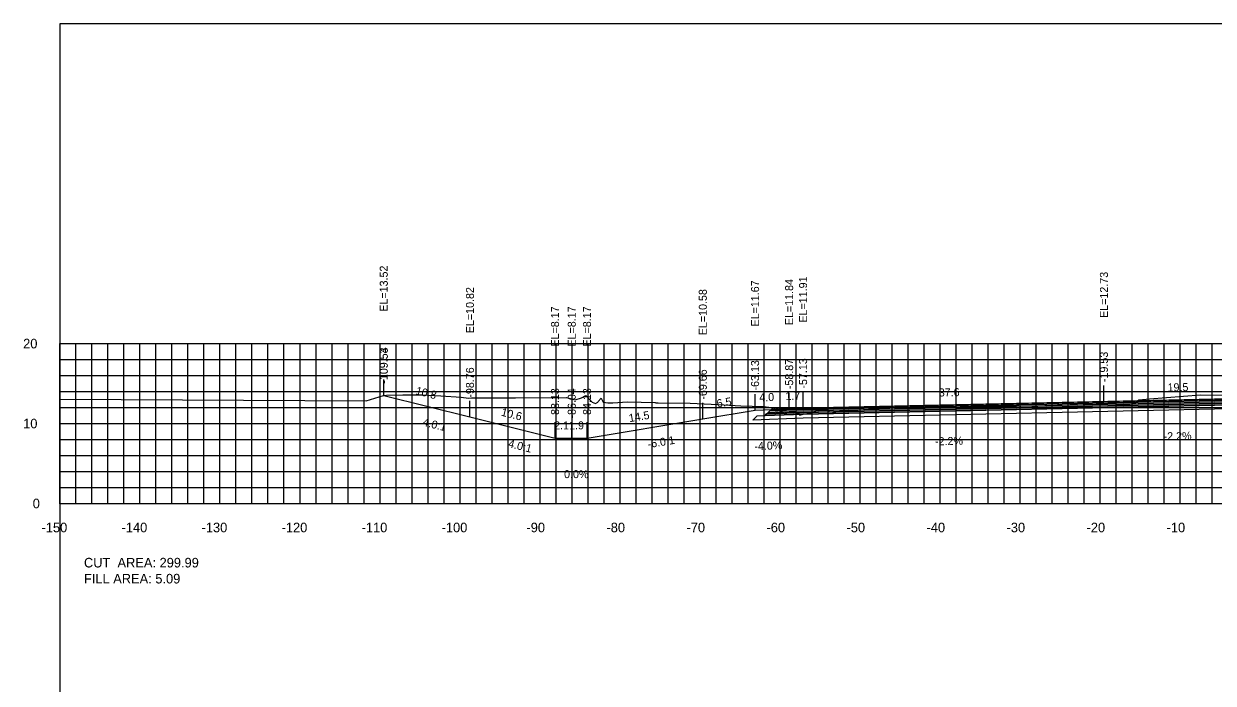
# Model space of a CAD drawing. Extents: x 1797419 to 1809236, y 248759 to 251512.
# Drawn here: x 1802476.5 to 1802625.1, y 250186.9 to 250269.4 of the extents above; entities that cross this region are included whole.
import ezdxf

# ---------------------------------------------------------------- set-up
doc = ezdxf.new("R2010")
doc.units = 0
for name, color, linetype in [('10', 7, 'Continuous'), ('3', 7, 'Continuous'), ('31', 7, 'Continuous'), ('4', 7, 'Continuous'), ('60', 7, 'Continuous'), ('ANNO-TXT', 7, 'Continuous'), ('BASE', 7, 'Continuous'), ('CL-CNST', 7, 'Continuous'), ('Level 62', 7, 'Continuous'), ('LOWER BINDER', 7, 'Continuous'), ('M-ROADS', 7, 'Continuous'), ('UPPER BINDER', 7, 'Continuous'), ('WEARING', 7, 'Continuous')]:
    doc.layers.add(name, color=color, linetype=linetype)

msp = doc.modelspace()

# ---------------------------------------------------------------- linework, layer by layer
for p, q in [((1802521.46, 250222.95), (1802521.46, 250224.95)), ((1802521.47, 250222.95), (1802521.47, 250224.95)), ((1802611.47, 250222.17), (1802611.47, 250224.17)), ((1802567.87, 250221.1), (1802567.87, 250223.1)), ((1802572.13, 250221.27), (1802572.13, 250223.27)), ((1802573.87, 250221.34), (1802573.87, 250223.34)), ((1802573.87, 250221.34), (1802573.87, 250223.34)), ((1802532.24, 250220.26), (1802532.24, 250222.26)), ((1802561.34, 250220.01), (1802561.34, 250222.01)), ((1802542.87, 250217.6), (1802542.87, 250219.6)), ((1802542.87, 250217.6), (1802542.87, 250219.6)), ((1802544.96, 250217.6), (1802544.96, 250219.6)), ((1802546.87, 250217.6), (1802546.87, 250219.6)), ((1802546.87, 250217.6), (1802546.87, 250219.6))]:
    msp.add_line(p, q)
msp.add_lwpolyline([(1802481, 250079.43), (1802781, 250079.43), (1802781, 250269.43), (1802481, 250269.43)], close=True)
at = {"layer": '60'}
for p, q in [((1802480.94, 250229.43), (1802481, 250229.43)), ((1802481, 250209.43), (1802481, 250229.43)), ((1802480.94, 250219.43), (1802481, 250219.43)), ((1802480.94, 250209.43), (1802481, 250209.43)), ((1802481, 250209.43), (1802781, 250209.43)), ((1802481, 250209.37), (1802481, 250209.43)), ((1802491, 250209.37), (1802491, 250209.43)), ((1802501, 250209.37), (1802501, 250209.43)), ((1802511, 250209.37), (1802511, 250209.43)), ((1802521, 250209.37), (1802521, 250209.43)), ((1802531, 250209.37), (1802531, 250209.43)), ((1802541, 250209.37), (1802541, 250209.43)), ((1802551, 250209.37), (1802551, 250209.43)), ((1802561, 250209.37), (1802561, 250209.43)), ((1802571, 250209.37), (1802571, 250209.43)), ((1802581, 250209.37), (1802581, 250209.43)), ((1802591, 250209.37), (1802591, 250209.43)), ((1802601, 250209.37), (1802601, 250209.43)), ((1802611, 250209.37), (1802611, 250209.43)), ((1802621, 250209.37), (1802621, 250209.43))]:
    msp.add_line(p, q, dxfattribs=at)
at = {"layer": 'BASE'}
msp.add_lwpolyline([(1802568.12, 250220.39), (1802569.12, 250220.43), (1802573.87, 250220.62), (1802631, 250221.87), (1802702.76, 250221.87), (1802707.51, 250221.69), (1802708.51, 250221.65), (1802709.03, 250221.12), (1802702.76, 250221.37), (1802631, 250221.37), (1802573.87, 250220.12), (1802567.6, 250219.87)], close=True, dxfattribs=at)
at = {"layer": 'CL-CNST'}
msp.add_lwpolyline([(1802521.46, 250222.95), (1802521.47, 250222.95), (1802532.24, 250220.26), (1802542.87, 250217.6), (1802542.87, 250217.6), (1802544.96, 250217.6), (1802546.87, 250217.6), (1802546.87, 250217.6), (1802561.34, 250220.01), (1802567.87, 250221.1), (1802569.87, 250221.18), (1802570.15, 250221.19), (1802572.13, 250221.27), (1802573.87, 250221.34), (1802573.87, 250221.34), (1802611.47, 250222.17), (1802631, 250222.59)], dxfattribs=at)
at = {"layer": 'Level 62'}
for p, q in [((1802481, 250229.43), (1802781, 250229.43)), ((1802481, 250209.43), (1802481, 250229.43)), ((1802483, 250209.43), (1802483, 250229.43)), ((1802485, 250209.43), (1802485, 250229.43)), ((1802487, 250209.43), (1802487, 250229.43)), ((1802489, 250209.43), (1802489, 250229.43)), ((1802491, 250209.43), (1802491, 250229.43)), ((1802493, 250209.43), (1802493, 250229.43)), ((1802495, 250209.43), (1802495, 250229.43)), ((1802497, 250209.43), (1802497, 250229.43)), ((1802499, 250209.43), (1802499, 250229.43)), ((1802501, 250209.43), (1802501, 250229.43)), ((1802503, 250209.43), (1802503, 250229.43)), ((1802505, 250209.43), (1802505, 250229.43)), ((1802507, 250209.43), (1802507, 250229.43)), ((1802509, 250209.43), (1802509, 250229.43)), ((1802511, 250209.43), (1802511, 250229.43)), ((1802513, 250209.43), (1802513, 250229.43)), ((1802515, 250209.43), (1802515, 250229.43)), ((1802517, 250209.43), (1802517, 250229.43)), ((1802519, 250209.43), (1802519, 250229.43)), ((1802521, 250209.43), (1802521, 250229.43)), ((1802523, 250209.43), (1802523, 250229.43)), ((1802525, 250209.43), (1802525, 250229.43)), ((1802527, 250209.43), (1802527, 250229.43)), ((1802529, 250209.43), (1802529, 250229.43)), ((1802531, 250209.43), (1802531, 250229.43)), ((1802533, 250209.43), (1802533, 250229.43)), ((1802535, 250209.43), (1802535, 250229.43)), ((1802537, 250209.43), (1802537, 250229.43)), ((1802539, 250209.43), (1802539, 250229.43)), ((1802541, 250209.43), (1802541, 250229.43)), ((1802543, 250209.43), (1802543, 250229.43)), ((1802545, 250209.43), (1802545, 250229.43)), ((1802547, 250209.43), (1802547, 250229.43)), ((1802549, 250209.43), (1802549, 250229.43)), ((1802551, 250209.43), (1802551, 250229.43)), ((1802553, 250209.43), (1802553, 250229.43)), ((1802555, 250209.43), (1802555, 250229.43)), ((1802557, 250209.43), (1802557, 250229.43)), ((1802559, 250209.43), (1802559, 250229.43)), ((1802561, 250209.43), (1802561, 250229.43)), ((1802563, 250209.43), (1802563, 250229.43)), ((1802565, 250209.43), (1802565, 250229.43)), ((1802567, 250209.43), (1802567, 250229.43)), ((1802569, 250209.43), (1802569, 250229.43)), ((1802571, 250209.43), (1802571, 250229.43)), ((1802573, 250209.43), (1802573, 250229.43)), ((1802575, 250209.43), (1802575, 250229.43)), ((1802577, 250209.43), (1802577, 250229.43)), ((1802579, 250209.43), (1802579, 250229.43)), ((1802581, 250209.43), (1802581, 250229.43)), ((1802583, 250209.43), (1802583, 250229.43)), ((1802585, 250209.43), (1802585, 250229.43)), ((1802587, 250209.43), (1802587, 250229.43)), ((1802589, 250209.43), (1802589, 250229.43)), ((1802591, 250209.43), (1802591, 250229.43)), ((1802593, 250209.43), (1802593, 250229.43)), ((1802595, 250209.43), (1802595, 250229.43)), ((1802597, 250209.43), (1802597, 250229.43)), ((1802599, 250209.43), (1802599, 250229.43)), ((1802601, 250209.43), (1802601, 250229.43)), ((1802603, 250209.43), (1802603, 250229.43)), ((1802605, 250209.43), (1802605, 250229.43)), ((1802607, 250209.43), (1802607, 250229.43)), ((1802609, 250209.43), (1802609, 250229.43)), ((1802611, 250209.43), (1802611, 250229.43)), ((1802613, 250209.43), (1802613, 250229.43)), ((1802615, 250209.43), (1802615, 250229.43)), ((1802617, 250209.43), (1802617, 250229.43)), ((1802619, 250209.43), (1802619, 250229.43)), ((1802621, 250209.43), (1802621, 250229.43)), ((1802623, 250209.43), (1802623, 250229.43)), ((1802625, 250209.43), (1802625, 250229.43)), ((1802481, 250227.43), (1802781, 250227.43)), ((1802481, 250225.43), (1802781, 250225.43)), ((1802481, 250223.43), (1802781, 250223.43)), ((1802481, 250221.43), (1802781, 250221.43)), ((1802481, 250219.43), (1802781, 250219.43)), ((1802481, 250217.43), (1802781, 250217.43)), ((1802481, 250215.43), (1802781, 250215.43)), ((1802481, 250213.43), (1802781, 250213.43)), ((1802481, 250211.43), (1802781, 250211.43)), ((1802481, 250209.43), (1802781, 250209.43))]:
    msp.add_line(p, q, dxfattribs=at)
at = {"layer": 'LOWER BINDER'}
for points in [[(1802573.87, 250220.81), (1802631, 250222.06), (1802702.76, 250222.06), (1802707.31, 250221.88), (1802707.51, 250221.69), (1802702.76, 250221.87), (1802631, 250221.87), (1802573.87, 250220.62), (1802569.12, 250220.43), (1802569.32, 250220.63)], [(1802573.87, 250221), (1802631, 250222.25), (1802702.76, 250222.25), (1802707.12, 250222.08), (1802707.31, 250221.88), (1802702.76, 250222.06), (1802631, 250222.06), (1802573.87, 250220.81), (1802569.32, 250220.63), (1802569.52, 250220.82)]]:
    msp.add_lwpolyline(points, close=True, dxfattribs=at)
at = {"layer": 'M-ROADS'}
msp.add_lwpolyline([(1802481, 250222.49), (1802519.26, 250222.28), (1802521.44, 250222.95), (1802521.81, 250223), (1802523.87, 250223.02), (1802524.01, 250223.02), (1802524.47, 250223.02), (1802526.23, 250223.01), (1802528.58, 250222.89), (1802531.14, 250222.72), (1802532.04, 250222.6), (1802532.44, 250222.66), (1802534.56, 250222.66), (1802535.31, 250222.66), (1802536.86, 250222.66), (1802537.32, 250222.65), (1802537.48, 250222.64), (1802537.94, 250222.64), (1802544.3, 250222.69), (1802545.37, 250222.41), (1802546.2, 250222.66), (1802546.72, 250222.95), (1802547.51, 250222.11), (1802547.91, 250221.94), (1802548.2, 250222.09), (1802548.26, 250222.17), (1802548.65, 250222.6), (1802548.9, 250222.12), (1802549.47, 250222), (1802549.57, 250222.01), (1802549.87, 250222), (1802550.08, 250222), (1802551.94, 250222.13), (1802555.34, 250222.06), (1802555.38, 250222.08), (1802555.46, 250222.01), (1802555.77, 250222), (1802559.74, 250221.99), (1802563.24, 250221.81), (1802566.11, 250221.64), (1802568.91, 250221.56), (1802569.92, 250221.44), (1802570.26, 250221.12), (1802570.34, 250221.43), (1802570.35, 250221.43), (1802570.85, 250221.23), (1802571.72, 250220.6), (1802572.02, 250220.88), (1802572.78, 250220.87), (1802572.89, 250220.9), (1802573.01, 250220.81), (1802573.35, 250220.64), (1802573.45, 250220.48), (1802573.45, 250220.49), (1802573.59, 250220.51), (1802574.05, 250220.65), (1802574.9, 250220.78), (1802575.24, 250220.91), (1802575.5, 250221.1), (1802575.83, 250221.17), (1802576.67, 250221.2), (1802577.14, 250220.94), (1802577.74, 250220.82), (1802578.04, 250220.92), (1802578.75, 250221.04), (1802584.73, 250221.38), (1802586.78, 250221.43), (1802588.39, 250221.44), (1802588.96, 250221.44), (1802589.1, 250221.43), (1802589.46, 250221.41), (1802590.85, 250221.42), (1802591.73, 250221.43), (1802593.51, 250221.48), (1802597.45, 250221.6), (1802598.27, 250221.63), (1802600.32, 250221.66), (1802600.38, 250221.66), (1802600.4, 250221.66), (1802600.85, 250221.63), (1802601.1, 250221.61), (1802603.03, 250221.64), (1802603.13, 250221.64), (1802603.22, 250221.64), (1802604.08, 250221.67), (1802607.22, 250221.77), (1802610.51, 250221.87), (1802610.68, 250221.88), (1802612.88, 250221.89), (1802613.26, 250221.81), (1802613.33, 250221.84), (1802613.35, 250221.84), (1802613.69, 250221.86), (1802614.41, 250221.87), (1802615.1, 250221.92), (1802615.15, 250221.92), (1802615.24, 250221.93), (1802615.26, 250221.92), (1802615.85, 250222.39), (1802615.85, 250222.39), (1802615.86, 250222.4), (1802617.16, 250222.54), (1802623.55, 250223.04), (1802629.65, 250222.94)], dxfattribs=at)
at = {"layer": 'UPPER BINDER'}
msp.add_lwpolyline([(1802702.76, 250222.25), (1802707.12, 250222.08), (1802706.92, 250222.28), (1802702.76, 250222.44), (1802631, 250222.44), (1802573.87, 250221.19), (1802569.72, 250221.02), (1802569.52, 250220.82), (1802573.87, 250221), (1802631, 250222.25)], close=True, dxfattribs=at)
at = {"layer": 'WEARING'}
msp.add_lwpolyline([(1802702.76, 250222.44), (1802706.92, 250222.28), (1802706.76, 250222.43), (1802702.76, 250222.59), (1802631, 250222.59), (1802573.87, 250221.34), (1802569.87, 250221.18), (1802569.72, 250221.02), (1802573.87, 250221.19), (1802631, 250222.44)], close=True, dxfattribs=at)

# ---------------------------------------------------------------- texts
for s, rotation, p in [('4.0:1', 345.9652, (1802526.25, 250219.18)), ('4.0:1', 345.9652, (1802536.95, 250216.5)), ('-6.0:1', 9.4623, (1802554.52, 250216.34))]:
    msp.add_text(s, height=1, rotation=rotation).set_placement(p)
at = {"layer": '10'}
for s, p in [('-150', (1802478.7, 250205.83)), ('-140', (1802488.7, 250205.83)), ('-130', (1802498.7, 250205.83)), ('-120', (1802508.7, 250205.83)), ('-110', (1802518.7, 250205.83)), ('-100', (1802528.7, 250205.83)), ('-90', (1802539.3, 250205.83)), ('-80', (1802549.3, 250205.83)), ('-70', (1802559.3, 250205.83)), ('-60', (1802569.3, 250205.83)), ('-50', (1802579.3, 250205.83)), ('-40', (1802589.3, 250205.83)), ('-30', (1802599.3, 250205.83)), ('-20', (1802609.3, 250205.83)), ('-10', (1802619.3, 250205.83))]:
    msp.add_text(s, height=1.2, dxfattribs=at).set_placement(p)
at = {"layer": '3'}
for s, p in [('EL=13.52', (1802521.96, 250233.42)), ('EL=13.52', (1802521.97, 250233.42)), ('EL=11.84', (1802572.63, 250231.74)), ('EL=11.91', (1802574.37, 250232.06)), ('EL=11.91', (1802574.37, 250232.06)), ('EL=12.73', (1802611.97, 250232.64)), ('EL=10.82', (1802532.74, 250230.73)), ('EL=10.58', (1802561.84, 250230.48)), ('EL=11.67', (1802568.37, 250231.57)), ('EL=8.17', (1802543.37, 250229.06)), ('EL=8.17', (1802543.37, 250229.06)), ('EL=8.17', (1802545.46, 250229.06)), ('EL=8.17', (1802547.37, 250229.06)), ('EL=8.17', (1802547.37, 250229.06)), ('-109.54', (1802521.96, 250224.42)), ('-109.53', (1802521.97, 250224.41)), ('-63.13', (1802568.37, 250223.56)), ('-58.87', (1802572.63, 250223.73)), ('-57.13', (1802574.37, 250223.8)), ('-57.13', (1802574.37, 250223.8)), ('-19.53', (1802611.97, 250224.62)), ('-98.76', (1802532.74, 250222.67)), ('-69.66', (1802561.84, 250222.42)), ('-88.13', (1802543.37, 250220.06)), ('-88.13', (1802543.37, 250220.06)), ('-86.04', (1802545.46, 250220.06)), ('-84.13', (1802547.37, 250220.06)), ('-84.13', (1802547.37, 250220.06))]:
    msp.add_text(s, height=1, rotation=90, dxfattribs=at).set_placement(p)
at = {"layer": '31'}
for s, p in [('20', (1802476.4, 250228.83)), ('10', (1802476.4, 250218.83)), ('0', (1802477.6, 250208.83))]:
    msp.add_text(s, height=1.2, dxfattribs=at).set_placement(p)
at = {"layer": '4'}
for s, rotation, p in [('10.8', 345.9652, (1802525.39, 250223.1)), ('19.5', 1.2595, (1802619.43, 250223.44)), ('6.5', 9.4623, (1802563.16, 250221.43)), ('4.0', 2.2903, (1802568.41, 250222.19)), ('1.7', 2.2902, (1802571.68, 250222.35)), ('37.6', 1.2595, (1802590.84, 250222.81)), ('10.6', 345.9652, (1802536.07, 250220.43)), ('14.5', 9.4623, (1802552.17, 250219.6)), ('-2.2%', 1.2595, (1802618.94, 250217.33)), ('-4.0%', 2.2903, (1802567.8, 250216.09)), ('-2.2%', 1.2595, (1802590.37, 250216.7))]:
    msp.add_text(s, height=1, rotation=rotation, dxfattribs=at).set_placement(p)
for s, p in [('2.1', (1802542.76, 250218.7)), ('1.9', (1802544.63, 250218.7)), ('0.0%', (1802544, 250212.6))]:
    msp.add_text(s, height=1, dxfattribs=at).set_placement(p)
at = {"layer": '60'}
msp.add_text('-', height=0.0001, dxfattribs=at).set_placement((1802481, 250209.43))
at = {"layer": 'ANNO-TXT'}
for s, p in [('CUT  AREA: 299.99', (1802484, 250201.43)), ('FILL AREA: 5.09', (1802484, 250199.43))]:
    msp.add_text(s, height=1.2, dxfattribs=at).set_placement(p)

doc.saveas('drawing.dxf')
